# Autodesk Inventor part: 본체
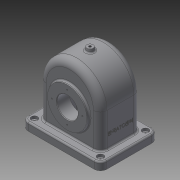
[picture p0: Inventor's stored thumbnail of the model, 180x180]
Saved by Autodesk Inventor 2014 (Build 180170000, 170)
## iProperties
Created: 2016-10
Part Number: 본체
Material: 일반
Document SubType Name: Modeling
Designer: USER
Density: 1 g/cm^3
Appearance: 기본값
Author: USER
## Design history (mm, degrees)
sketch "스케치1"
  geometry: L1 (0, 0)-(58, 0); L2 (58, 0)-(58, 65); L3 (-58, 65)-(-58, 0); L4 (-58, 0)-(0, 0); A1 r 58 centre (0, 65) between (58, 65) and (-58, 65)
  constraints: 8 end point, 2 horizontal, 2 point on circle, 2 tangent, 1 centre point, 1 parallel, 1 perpendicular, 1 vertical alignment
  dimensions: "d0" = 58 radius of A1; "d1" = 65 distance from line of L1 L2.end
extrude "돌출1" new body sketch "스케치1" stored distance "d2" = 77; taper "d3" = 0 deg
sketch "스케치2"
  geometry: L1 (75, 0)-(-75, 0); L2 (-75, 0)-(-75, -15); L3 (-75, -15)-(75, -15); L4 (75, -15)-(75, 0); 2 further points
  constraints: 8 end point, 2 parallel, 1 coincident, 1 horizontal, 1 midpoint, 1 perpendicular
  dimensions: "d4" = 15 distance of L1.end L2.end; "d5" = 150 distance of L2.end L3.end
extrude "돌출2" join sketch "스케치2" stored distance "d6" = 110; taper "d7" = 0 deg
sketch "스케치3"
  geometry: L1 (-75, -15)-(75, -15) reference; C1 r 31 at (0, 50); A1 r 58 centre (0, 65) between (58, 65) and (-58, 65) reference; 1 further point
  constraints: 1 centre point, 1 vertical alignment
  dimensions: "d8" = 62 diameter of C1; "d9" = 65 distance from line of L1 C1.centre
extrude "돌출3" join sketch "스케치3" distance "d10" = 87; taper "d11" = 0 deg
sketch "스케치4"
  geometry: L1 (-75, -15)-(75, -15) reference; C1 r 37.5 at (0, 50); A1 r 58 centre (0, 65) between (58, 65) and (-58, 65) reference; 1 further point
  constraints: 1 centre point, 1 vertical alignment
  dimensions: "d12" = 75 diameter of C1; "d13" = 65 distance from line of L1 C1.centre
extrude "돌출4" join sketch "스케치4" distance "d14" = 5; taper "d15" = 0 deg
sketch "스케치5"
  geometry: L1 (-58, 65)-(-58, 0) reference; L2 (58, 0)-(58, 65) reference; L3 (-52, -15)-(-52, 65); L4 (52, 65)-(52, -15); L5 (-75, -15)-(75, -15) reference; L6 (52, -15)-(-52, -15); A1 r 58 centre (0, 65) between (58, 65) and (-58, 65) reference; A2 r 52 centre (0, 65) between (52, 65) and (-52, 65); 1 further point
  constraints: 6 end point, 2 point on circle, 2 point on line, 1 centre point, 1 collinear
  dimensions: "d16" = 6 radial gap between concentric circles of A1 A2; "d17" = 6 distance between parallel lines of L2 L4; "d18" = 6 distance between parallel lines of L1 L3
extrude "돌출5" cut sketch "스케치5" stored distance "d19" = 67; taper "d20" = 0 deg
sketch "스케치6"
  geometry: L1 (-33.5, 117)-(-33.5, 65) reference; L2 (-33.5, 65)-(-33.5, -15) reference; L3 (-43.5, 87.5)-(-43.5, 12.5) reference; L4 (-33.5, 89.747)-(-19.5, 78); L5 (-19.5, 78)-(-19.5, 50); L6 (-19.5, 50)-(-33.5, 50); L7 (-33.5, 89.747)-(-33.5, 50); 1 further point
  constraints: 8 end point, 2 perpendicular, 2 point on line, 1 horizontal alignment, 1 midpoint, 1 parallel
  dimensions: "d25" = 24 distance between parallel lines of L3 L5; "d26" = 50 deg angle of L4 L5; "d27" = 56 diameter of L4.end L6
revolve "회전1" sketch "스케치6" stored, may be unused: angle "d28" = 90 deg
fillet "모깎기1" dims "d29" = 3
hole "구멍1" diameter "d32" = 40; stored, may be unused: countersink angle "d36" = 90 deg, drill point angle "d38" = 118 deg; dims "d30" = 10, "d31" = 10, "d33" = 6, "d34" = 4, "d35" = 2, "d37" = 8
chamfer "모따기1" distance "d39" = 1; stored, may be unused: second distance "d40" = 2, angle "d41" = 45 deg
sketch "스케치7"
  geometry: L1 (-33.5, 117)-(33.5, 117) reference; L2 (0, 117)-(0, 129); L3 (0, 129)-(6, 129); L4 (6, 129)-(8.116, 117); L5 (8.116, 117)-(0, 117); L6 (-55, -15)-(55, -15) reference; 1 further point
  constraints: 8 end point, 2 perpendicular, 1 collinear, 1 midpoint, 1 point on line
  dimensions: "d42" = 12 vertical distance of L3.end L2; "d43" = 100 deg angle of L1 L4; "d44" = 144 distance between parallel lines of L6 L3
revolve "회전2" sketch "스케치7" stored, may be unused: angle "d45" = 90 deg
fillet "모깎기2" dims "d46" = 3
hole "구멍2" diameter "d49" = 4.459; stored, may be unused: countersink angle "d53" = 90 deg, drill point angle "d55" = 118 deg; dims "d47" = 10, "d48" = 10, "d50" = 6, "d51" = 4, "d52" = 2, "d54" = 8
sketch "스케치8"
  geometry: C1 r 37.5 at (0, 0) reference; 2 further points
  constraints: 1 vertical alignment
  dimensions: "d56" = 29 distance of C1.centre point (0, 29)
hole "구멍3" sketch "스케치8" at (0, 29) diameter "d57" = 2.459; stored, may be unused: countersink angle "d61" = 90 deg, drill point angle "d63" = 118 deg; dims "d58" = 6, "d59" = 4, "d60" = 2, "d62" = 8
sketch "스케치9"
  geometry: C1 r 31 at (0, 0) reference; 2 further points
  constraints: 1 horizontal alignment
  dimensions: "d67" = 26 distance of C1.centre point (-26, 0)
hole "구멍4" sketch "스케치9" at (-26, 0) diameter "d68" = 2.459; stored, may be unused: countersink angle "d72" = 90 deg, drill point angle "d74" = 118 deg; dims "d69" = 6, "d70" = 4, "d71" = 2, "d73" = 8
fillet "모깎기3" dims "d78" = 12
hole "구멍5" diameter "d81" = 5; stored, may be unused: countersink angle "d85" = 90 deg, drill point angle "d87" = 0 deg; dims "d79" = 10, "d80" = 10, "d82" = 6, "d83" = 12, "d84" = 5, "d86" = 8
fillet "모깎기4" dims "d94" = 8
fillet "모깎기5" dims "d95" = 13
fillet "모깎기6" dims "d96" = 3
node "작업 평면1"
sketch "스케치10"
  geometry: L1 (-43, -15)-(43, -15) reference; L2 (-38.5, 65)-(-38.5, 110) reference; 2 further points
  constraints: 1 other
  dimensions: "d98" = 38.5 distance from line of point (0, 25) L2; "d99" = 40 distance from line of L1 point (0, 25)
feature "엠보싱1" sketch "스케치10" dims "d0" = 58, "d1" = 65, "d100" = 0.5, "d101" = 0
node "솔리드1"
pattern_circular "원형 패턴1" dims angle "d65" = 360 deg
pattern_circular "원형 패턴2" dims angle "d76" = 360 deg
pattern_linear "직사각형 패턴1" dims "d90" = 126, "d93" = 86
other parameters: "d97" = 128.5
